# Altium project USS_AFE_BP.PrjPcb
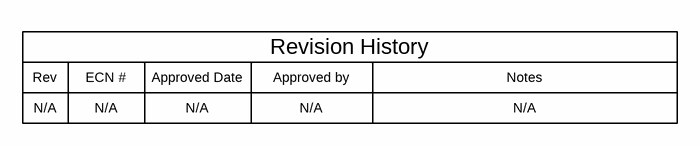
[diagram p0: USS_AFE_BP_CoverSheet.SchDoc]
TID: TIDM-1002; TechSupport: http://www.ti.com/support; SCH_Rev: 1.0; PRJ_Title: USS-AFE-BP; PRJ_Number: USS-AFE-BP; PRJ_Engineer: Luis Reynoso; PRJ_Customer: Public Release; PCB_Rev: RevA; PCB_Layout: A0272600; EVM_Orderable: USS-AFE-BP; CopyrightYear: 2016
3 sheets, 120 parts. Net scope: global (net labels, ports and power ports of the same name join across sheets).
Board file: USS_AFE_BP.PcbDoc
Sheets:
  USS_AFE_BP_CoverSheet.SchDoc
  USS_AFE_BP_AFE.SchDoc
  USS_AFE_BP_Hardware.SchDoc

## Sheet USS_AFE_BP_CoverSheet.SchDoc: Cover Sheet
size 431 x 279 mm; Date: Not shown in title block; ApprovedBy: Not shown in title block; CheckedBy: Not shown in title block; Author: Not shown in title block; CompanyName: Not shown in title block; Engineer: Not shown in title block; Organization: Not shown in title block; Address1: Not shown in title block; Address2: Not shown in title block; Address3: Not shown in title block; Address4: Not shown in title block; DocumentNumber: 1; Revision: Use project parameter SCH_Rev; SheetNumber: 1; SheetTotal: 3; PageSetup: Record=PageOptions¦CenterHorizontal=True¦CenterVertical=True¦PrintScale=1.00¦XCorrection=1.00¦YCorrection=1.00¦PrintKind=0¦BorderSize=5000000¦LeftOffset=0¦BottomOffset=0¦Orientation=2¦PaperLength=1000¦PaperWidth=1000¦Scale=100¦PaperSource=15¦PrintQuality=600¦MediaType=1¦DitherType=10¦PaperKind=Letter¦PrintScaleMode=1

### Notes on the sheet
- Rev
- N/A
- ECN #
- Approved Date
- Approved by
- Revision History
- Notes

## Sheet USS_AFE_BP_AFE.SchDoc: GAS AFE
size 431 x 279 mm; Date: Not shown in title block; ApprovedBy: Not shown in title block; CheckedBy: Not shown in title block; Author: Not shown in title block; CompanyName: Not shown in title block; Engineer: Not shown in title block; Organization: Not shown in title block; Address1: Not shown in title block; Address2: Not shown in title block; Address3: Not shown in title block; Address4: Not shown in title block; DocumentNumber: 1; Revision: Use project parameter SCH_Rev; SheetNumber: 2; SheetTotal: 3; PageSetup: Record=PageOptions¦CenterHorizontal=True¦CenterVertical=True¦PrintScale=0.62¦XCorrection=1.00¦YCorrection=1.00¦PrintKind=0¦BorderSize=5000000¦LeftOffset=0¦BottomOffset=0¦Orientation=2¦PaperLength=1000¦PaperWidth=1000¦Scale=100¦PaperSource=15¦PrintQuality=600¦MediaType=1¦DitherType=10¦PrintScaleMode=1¦PaperKind=Letter
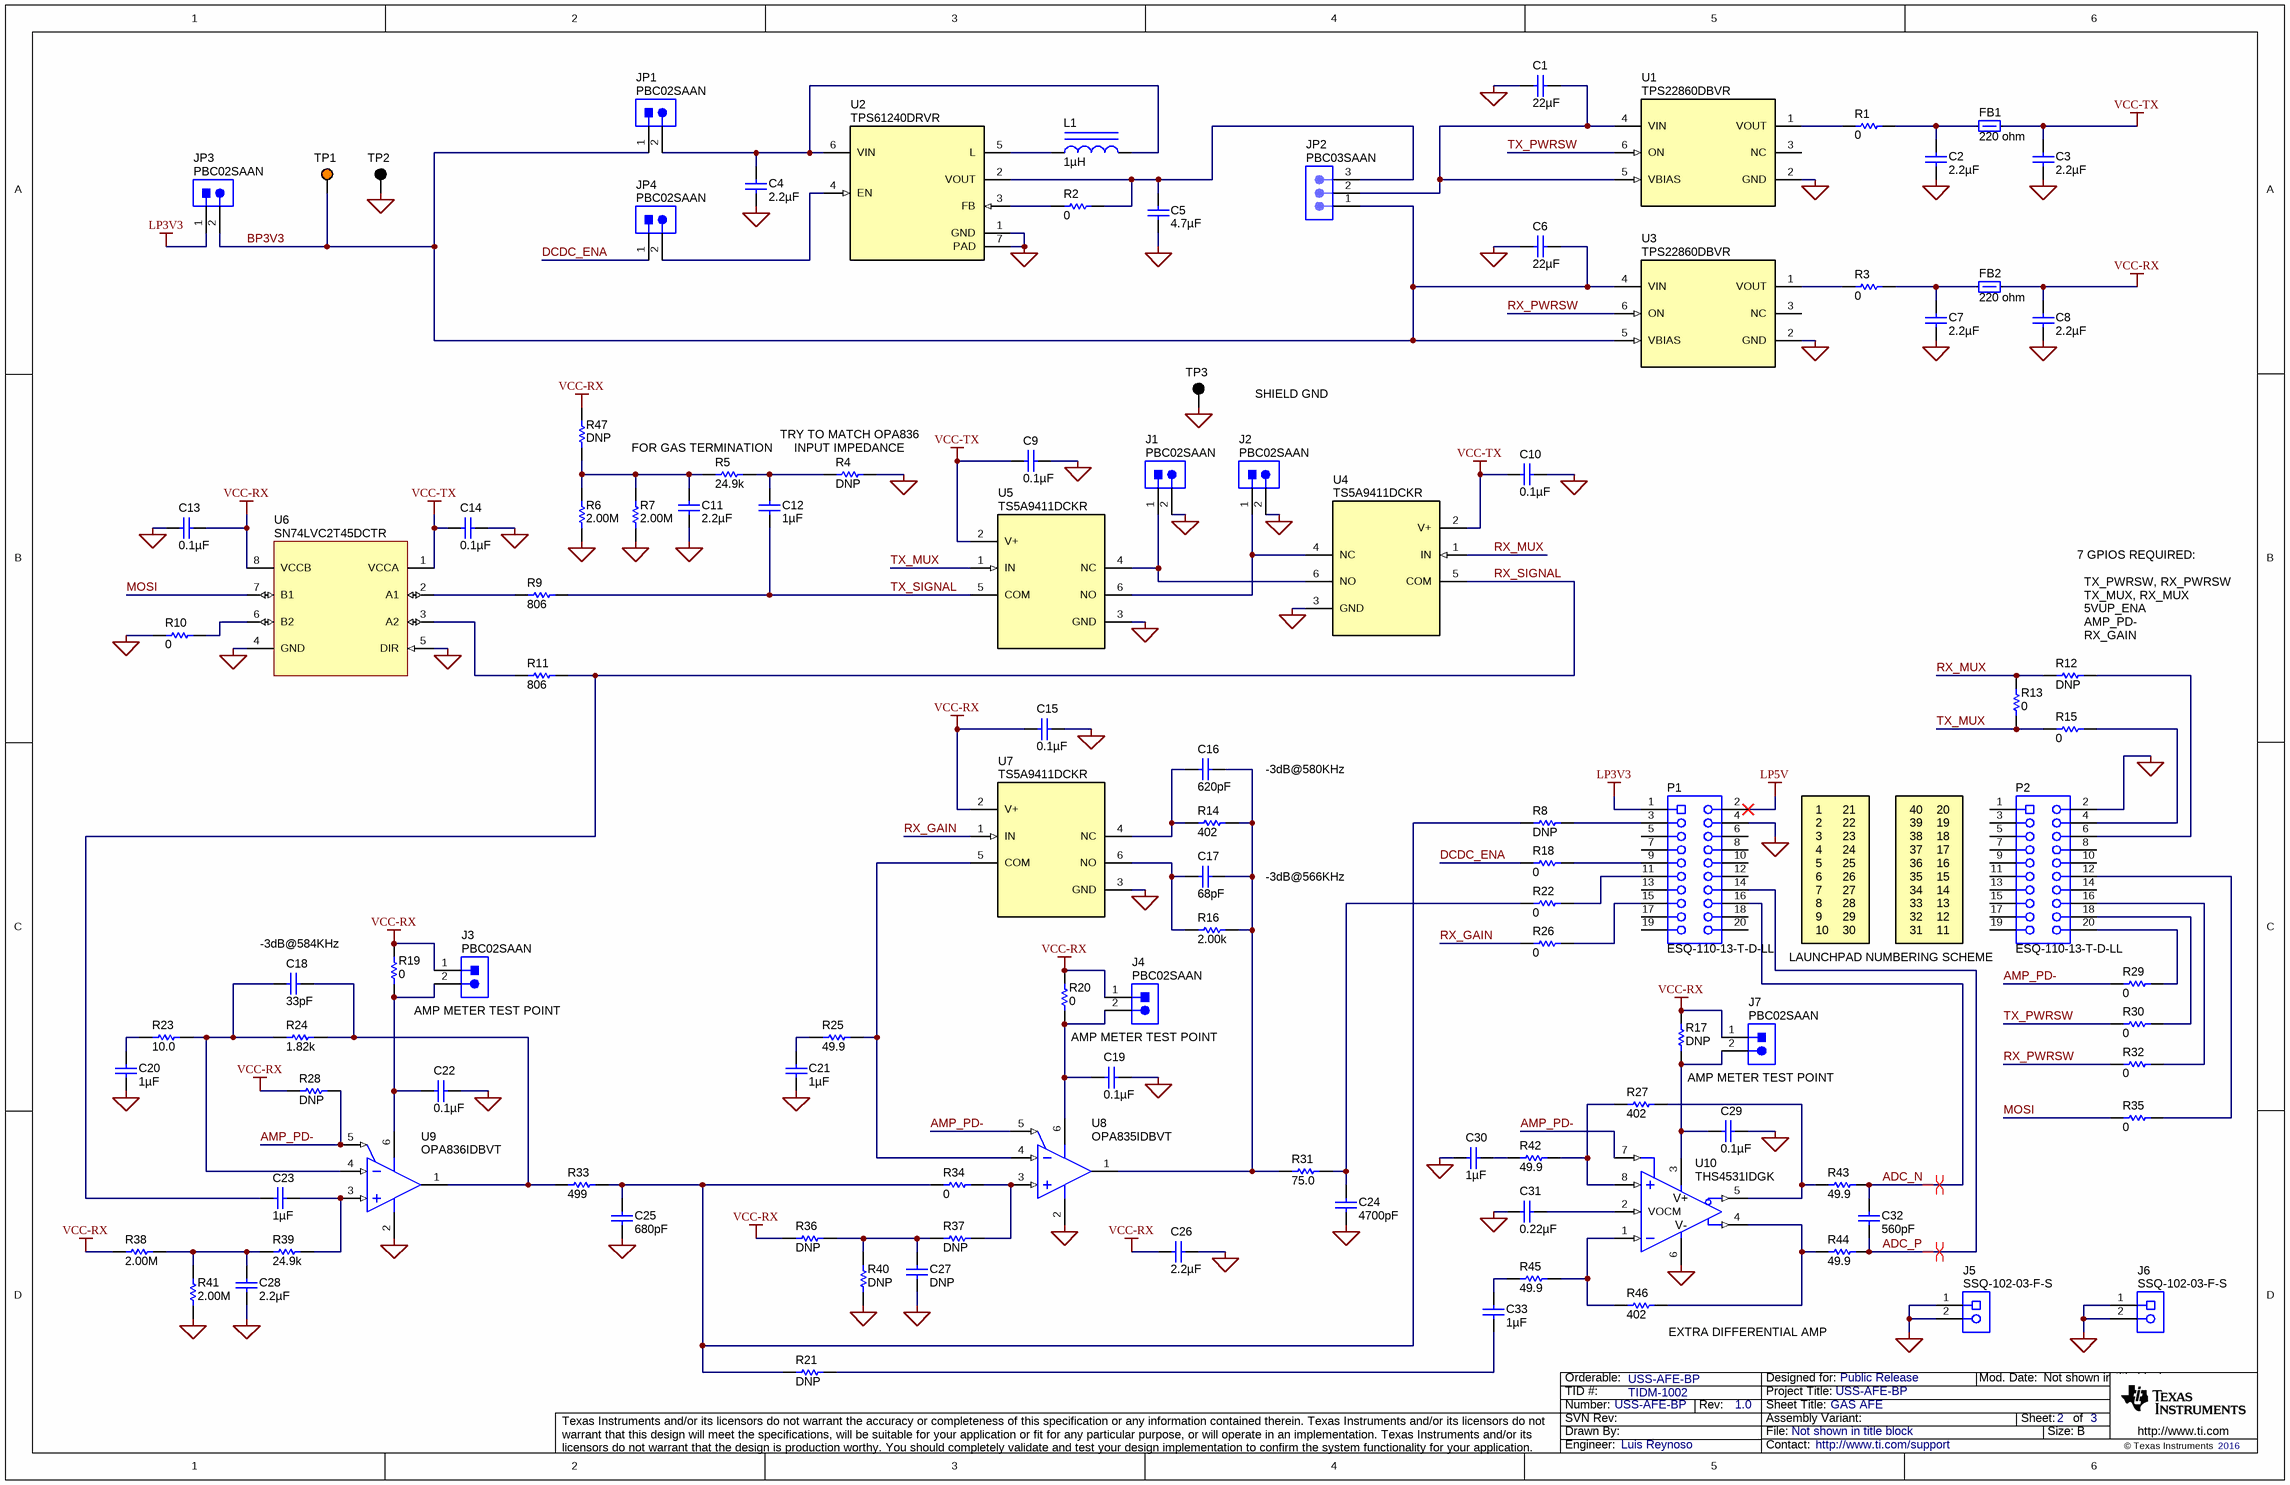
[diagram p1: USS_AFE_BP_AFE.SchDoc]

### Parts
C1  ValueDisplayed: 22µF  [0603]  (hidden comment: CL10A226MP8NUNE)
C2  ValueDisplayed: 2.2µF  [0603]  (hidden comment: GRM188R61C225KE15D)
C3  ValueDisplayed: 2.2µF  [0603]  (hidden comment: GRM188R61C225KE15D)
C4  ValueDisplayed: 2.2µF  [0603]  (hidden comment: GRM188R61C225KE15D)
C5  ValueDisplayed: 4.7µF  [0603]  (hidden comment: GRM188R61C475KAAJ)
C6  ValueDisplayed: 22µF  [0603]  (hidden comment: CL10A226MP8NUNE)
C7  ValueDisplayed: 2.2µF  [0603]  (hidden comment: GRM188R61C225KE15D)
C8  ValueDisplayed: 2.2µF  [0603]  (hidden comment: GRM188R61C225KE15D)
C9  ValueDisplayed: 0.1µF  [0603]  (hidden comment: GRM188R71E104KA01D)
C10  ValueDisplayed: 0.1µF  [0603]  (hidden comment: GRM188R71E104KA01D)
C11  ValueDisplayed: 2.2µF  [0603]  (hidden comment: GRM188R61C225KE15D)
C12  ValueDisplayed: 1µF  [0603]  (hidden comment: GRM188R71C105KA12D)
C13  ValueDisplayed: 0.1µF  [0603]  (hidden comment: GRM188R71E104KA01D)
C14  ValueDisplayed: 0.1µF  [0603]  (hidden comment: GRM188R71E104KA01D)
C15  ValueDisplayed: 0.1µF  [0603]  (hidden comment: GRM188R71E104KA01D)
C16  ValueDisplayed: 620pF  [0603]  (hidden comment: GRM1885C1H621JA01D)
C17  ValueDisplayed: 68pF  [0603]  (hidden comment: GRM1885C1H680JA01D)
C18  ValueDisplayed: 33pF  [0603]  (hidden comment: GRM1885C1H330JA01D)
C19  ValueDisplayed: 0.1µF  [0603]  (hidden comment: GRM188R71E104KA01D)
C20  ValueDisplayed: 1µF  [0603]  (hidden comment: GRM188R71C105KA12D)
C21  ValueDisplayed: 1µF  [0603]  (hidden comment: GRM188R71C105KA12D)
C22  ValueDisplayed: 0.1µF  [0603]  (hidden comment: GRM188R71E104KA01D)
C23  ValueDisplayed: 1µF  [0603]  (hidden comment: GRM188R71C105KA12D)
C24  ValueDisplayed: 4700pF  [0603_HV]  (hidden comment: C0603C472J5RACTU)
C25  ValueDisplayed: 680pF  [0603]  (hidden comment: GRM1885C1H681JA01D)
C26  ValueDisplayed: 2.2µF  [0603]  (hidden comment: GRM188R61C225KE15D)
C27  ValueDisplayed: DNP  [0603]  (hidden comment: GRM188R61C225KE15D)
C28  ValueDisplayed: 2.2µF  [0603]  (hidden comment: GRM188R61C225KE15D)
C29  ValueDisplayed: 0.1µF  [0603]  (hidden comment: GRM188R71E104KA01D)
C30  ValueDisplayed: 1µF  [0603]  (hidden comment: GRM188R71C105KA12D)
C31  ValueDisplayed: 0.22µF  [0603]  (hidden comment: GRM188R71A224KA01D)
C32  ValueDisplayed: 560pF  [0603]  (hidden comment: GRM188R71H561KA01D)
C33  ValueDisplayed: 1µF  [0603]  (hidden comment: GRM188R71C105KA12D)
FB1  value 220 ohm  [0603]  (hidden comment: MPZ1608S221A)
FB2  value 220 ohm  [0603]  (hidden comment: MPZ1608S221A)
J1  PBC02SAAN  [Sullins_PBC02SAAN]
J2  PBC02SAAN  [Sullins_PBC02SAAN]
J3  PBC02SAAN  [Sullins_PBC02SAAN]
J4  PBC02SAAN  [Sullins_PBC02SAAN]
J5  SSQ-102-03-F-S  [Samtec_SSQ-102-03-x-S]
J6  SSQ-102-03-F-S  [Samtec_SSQ-102-03-x-S]
J7  PBC02SAAN  [Sullins_PBC02SAAN]
JP1  PBC02SAAN  [Sullins_PBC02SAAN]
JP2  PBC03SAAN  [PBC03SAAN]
JP3  PBC02SAAN  [Sullins_PBC02SAAN]
JP4  PBC02SAAN  [Sullins_PBC02SAAN]
L1  ValueDisplayed: 1µH  [0805_HV]  (hidden comment: LQM21PN1R0MC0D)
P1  ESQ-110-13-T-D-LL  [Samtec_ESQ-110-13-x-D-LL]
P2  ESQ-110-13-T-D-LL  [Samtec_ESQ-110-13-x-D-LL]
R1  ValueDisplayed: 0  [0603]  (hidden comment: RC0603JR-070RL)
R2  ValueDisplayed: 0  [0603]  (hidden comment: RC0603JR-070RL)
R3  ValueDisplayed: 0  [0603]  (hidden comment: RC0603JR-070RL)
R4  ValueDisplayed: DNP  [0603]  (hidden comment: RC0603FR-07200KL)
R5  ValueDisplayed: 24.9k  [0603]  (hidden comment: RC0603FR-0724K9L)
R6  ValueDisplayed: 2.00M  [0603]  (hidden comment: RC0603FR-072ML)
R7  ValueDisplayed: 2.00M  [0603]  (hidden comment: RC0603FR-072ML)
R8  ValueDisplayed: DNP  [0603]  (hidden comment: RC0603JR-070RL)
R9  ValueDisplayed: 806  [0603]  (hidden comment: RC0603FR-07806RL)
R10  ValueDisplayed: 0  [0603]  (hidden comment: RC0603JR-070RL)
R11  ValueDisplayed: 806  [0603]  (hidden comment: RC0603FR-07806RL)
R12  ValueDisplayed: DNP  [0603]  (hidden comment: RC0603JR-070RL)
R13  ValueDisplayed: 0  [0603]  (hidden comment: RC0603JR-070RL)
R14  ValueDisplayed: 402  [0603]  (hidden comment: RC0603FR-07402RL)
R15  ValueDisplayed: 0  [0603]  (hidden comment: RC0603JR-070RL)
R16  ValueDisplayed: 2.00k  [0603]  (hidden comment: RC0603FR-072KL)
R17  ValueDisplayed: DNP  [0603]  (hidden comment: RC0603JR-070RL)
R18  ValueDisplayed: 0  [0603]  (hidden comment: RC0603JR-070RL)
R19  ValueDisplayed: 0  [0603]  (hidden comment: RC0603JR-070RL)
R20  ValueDisplayed: 0  [0603]  (hidden comment: RC0603JR-070RL)
R21  ValueDisplayed: DNP  [0603]  (hidden comment: RC0603JR-070RL)
R22  ValueDisplayed: 0  [0603]  (hidden comment: RC0603JR-070RL)
R23  ValueDisplayed: 10.0  [0603]  (hidden comment: RC0603FR-0710RL)
R24  ValueDisplayed: 1.82k  [0603]  (hidden comment: RC0603FR-071K82L)
R25  ValueDisplayed: 49.9  [0603]  (hidden comment: RC0603FR-0749R9L)
R26  ValueDisplayed: 0  [0603]  (hidden comment: RC0603JR-070RL)
R27  ValueDisplayed: 402  [0603_HV]  (hidden comment: RC0603FR-07402RL)
R28  ValueDisplayed: DNP  [0603]  (hidden comment: RCG060310K0FKEA)
R29  ValueDisplayed: 0  [0603]  (hidden comment: RC0603JR-070RL)
R30  ValueDisplayed: 0  [0603]  (hidden comment: RC0603JR-070RL)
R31  ValueDisplayed: 75.0  [0603_HV]  (hidden comment: RC0603FR-0775RL)
R32  ValueDisplayed: 0  [0603]  (hidden comment: RC0603JR-070RL)
R33  ValueDisplayed: 499  [0603]  (hidden comment: RC0603FR-07499RL)
R34  ValueDisplayed: 0  [0603]  (hidden comment: RC0603JR-070RL)
R35  ValueDisplayed: 0  [0603]  (hidden comment: RC0603JR-070RL)
R36  ValueDisplayed: DNP  [0603]  (hidden comment: RC0603FR-072ML)
R37  ValueDisplayed: DNP  [0603]  (hidden comment: RC0603FR-0724K9L)
R38  ValueDisplayed: 2.00M  [0603]  (hidden comment: RC0603FR-072ML)
R39  ValueDisplayed: 24.9k  [0603]  (hidden comment: RC0603FR-0724K9L)
R40  ValueDisplayed: DNP  [0603]  (hidden comment: RC0603FR-072ML)
R41  ValueDisplayed: 2.00M  [0603]  (hidden comment: RC0603FR-072ML)
R42  ValueDisplayed: 49.9  [0603]  (hidden comment: RC0603FR-0749R9L)
R43  ValueDisplayed: 49.9  [0603]  (hidden comment: RC0603FR-0749R9L)
R44  ValueDisplayed: 49.9  [0603]  (hidden comment: RC0603FR-0749R9L)
R45  ValueDisplayed: 49.9  [0603]  (hidden comment: RC0603FR-0749R9L)
R46  ValueDisplayed: 402  [0603_HV]  (hidden comment: RC0603FR-07402RL)
R47  ValueDisplayed: DNP  [0603]  (hidden comment: RC0603FR-072ML)
TP1  5003  [Keystone5003]  (value not drawn)
TP2  5001  [Keystone5001]  (value not drawn)
TP3  5001  [Keystone5001]  (value not drawn)
U1  TPS22860DBVR  [DBV0006A_N]
U2  TPS61240DRVR  [DRV0006A]
U3  TPS22860DBVR  [DBV0006A_N]
U4  TS5A9411DCKR  [DCK0006A_N]
U5  TS5A9411DCKR  [DCK0006A_N]
U6  SN74LVC2T45DCTR  [DCT0008A_N]
U7  TS5A9411DCKR  [DCK0006A_N]
U8  OPA835IDBVT  [DBV0006A_N]
U9  OPA836IDBVT  [DBV0006A_N]
U10  THS4531IDGK  [DGK0008A_N]

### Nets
GND: C1.2 C2.2 C3.2 C4.2 C5.2 C6.2 C7.2 C8.2 C9.2 C10.2 C11.1 C13.1 C14.2 C15.2 C19.2 C20.1 C21.1 C22.2 C24.2 C25.2 C26.1 C27.1 C28.1 C29.2 C30.2 C31.2 J1.2 J2.2 J5.1 J5.2 J6.1 J6.2 P1.4 P2.2 R4.2 R6.1 R7.1 R10.2 R40.1 R41.1 TP2.1 TP3.1 U1.2(GND) U2.1(GND) U2.7(PAD) U3.2(GND) U4.3(GND) U5.3(GND) U6.4(GND) U6.5(DIR) U7.3(GND) U8.2(VS-) U9.2(VS-) U10.6(VS-)
LP3V3: JP3.1 P1.1
LP5V: P1.2
VCC-RX: C8.1 C13.2 C15.1 C26.2 FB2.2 J3.1 J4.1 J7.1 R17.2 R19.2 R20.2 R28.1 R36.2 R38.2 R47.2 U6.8(VCCB) U7.2(V+)
VCC-TX: C3.1 C9.1 C10.1 C14.1 FB1.2 U4.2(V+) U5.2(V+) U6.1(VCCA)
ADC_N: C32.1 P1.16 R43.2
ADC_P: C32.2 P1.14 R44.2
AMP_PD-: R28.2 R29.1 U8.5(~{PD}) U9.5(~{PD}) U10.7(~{PD})
BP3V3: C6.1 JP1.1 JP2.1 JP3.2 TP1.1 U3.4(VIN) U3.5(VBIAS)
DCDC_ENA: JP4.1 R18.1
MOSI: R35.1 U6.7(B1)
RX_GAIN: R26.1 U7.1(IN)
RX_MUX: R12.2 R13.1 U4.1(IN)
RX_PWRSW: R32.1 U3.6(ON)
RX_SIGNAL: C23.1 R11.2 U4.5(COM)
TX_MUX: R13.2 R15.2 U5.1(IN)
TX_PWRSW: R30.1 U1.6(ON)
TX_SIGNAL: C12.1 R9.2 U5.5(COM)
NetC1_1: C1.1 JP2.2 U1.4(VIN) U1.5(VBIAS)
NetC2_1: C2.1 FB1.1 R1.1
NetC4_1: C4.1 JP1.2 L1.2 U2.6(VIN)
NetC5_1: C5.1 JP2.3 R2.1 U2.2(VOUT)
NetC7_1: C7.1 FB2.1 R3.1
NetC11_2: C11.2 R5.1 R6.2 R7.2 R47.1
NetC12_2: C12.2 R4.1 R5.2
NetC16_1: C16.1 C17.1 R14.2 R16.2 R31.1 U8.1(VOUT)
NetC16_2: C16.2 R14.1 U7.4(NC)
NetC17_2: C17.2 R16.1 U7.6(NO)
NetC18_1: C18.1 R24.2 R33.1 U9.1(VOUT)
NetC18_2: C18.2 R23.2 R24.1 U9.4(VIN-)
NetC19_1: C19.1 J4.2 R20.1 U8.6(VS+)
NetC20_2: C20.2 R23.1
NetC21_2: C21.2 R25.1
NetC22_1: C22.1 J3.2 R19.1 U9.6(VS+)
NetC23_2: C23.2 R39.2 U9.3(VIN+)
NetC24_1: C24.1 R22.1 R31.2
NetC25_1: C25.1 R8.2 R21.2 R33.2 R34.2
NetC27_2: C27.2 R36.1 R37.1 R40.2
NetC28_2: C28.2 R38.1 R39.1 R41.2
NetC29_1: C29.1 J7.2 R17.1 U10.3(VS+)
NetC30_1: C30.1 R42.1
NetC31_1: C31.1 U10.2(VOCM)
NetC33_1: C33.1 R21.1
NetC33_2: C33.2 R45.1
NetJ1_1: J1.1 U4.6(NO) U5.4(NC)
NetJ2_1: J2.1 U4.4(NC) U5.6(NO)
NetJP4_2: JP4.2 U2.4(EN)
NetL1_1: L1.1 U2.5(L)
NetP1_3: P1.3 R8.1
NetP1_9: P1.9 R18.2
NetP1_11: P1.11 R22.2
NetP1_15: P1.15 R26.2
NetP2_4: P2.4 R15.1
NetP2_6: P2.6 R12.1
NetP2_12: P2.12 R35.2
NetP2_16: P2.16 R32.2
NetP2_18: P2.18 R30.2
NetP2_20: P2.20 R29.2
NetR1_2: R1.2 U1.1(VOUT)
NetR2_2: R2.2 U2.3(FB)
NetR3_2: R3.2 U3.1(VOUT)
NetR9_1: R9.1 U6.2(A1)
NetR10_1: R10.1 U6.6(B2)
NetR11_1: R11.1 U6.3(A2)
NetR25_2: R25.2 U7.5(COM) U8.4(VIN-)
NetR27_1: R27.1 R42.2 U10.8(VIN+)
NetR27_2: R27.2 R43.1 U10.5(VOUT-)
NetR34_1: R34.1 R37.2 U8.3(VIN+)
NetR44_1: R44.1 R46.2 U10.4(VOUT+)
NetR45_2: R45.2 R46.1 U10.1(VIN-)

Not connected (* = marked no-connect by the designer): P1 5 6 7 8 10 12 13 17 18 19 20; P2 1 3 5 7 8 9 10 11 13 14 15 17 19; U1 3(NC); U3 3(NC)

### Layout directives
differential pair: ADC_N, ADC_P

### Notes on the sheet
- (near R4) TRY TO MATCH OPA836
- SHIELD GND
- (near R5) FOR GAS TERMINATION
- (near R4) INPUT IMPEDANCE
- 7 GPIOS REQUIRED:
- 5VUP_ENA
- TX_PWRSW, RX_PWRSW
- TX_MUX, RX_MUX
- (near R12) AMP_PD-
- (near R12) RX_GAIN
- -3dB@580KHz
- 2
- 3
- 1
- 22
- 23
- 21
- 39
- 38
- 40
- 19
- 18
- 20
- -3dB@566KHz
- 4
- 5
- 6
- 7
- 8
- 24
- 25
- 26
- 27
- 28
- 37
- 36
- 35
- 34
- 33
- 17
- 16
- 15
- 14
- 13
- (near C18) -3dB@584KHz
- LAUNCHPAD NUMBERING SCHEME
- 9
- 10
- 29
- 30
- 32
- 31
- 12
- 11
- (near J3) AMP METER TEST POINT
- AMP METER TEST POINT
- (near R46) EXTRA DIFFERENTIAL AMP

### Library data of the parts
C1 C6 = CL10A226MP8NUNE: CAP, CERM, 22 µF, 10 V, +/- 20%, X5R, 0603; Manufacturer: Samsung Electro-Mechanics; Polarized: N; CompType: Capacitor; Value: 22uF; U/M: EA; Cap_F: 0.000022; Tolerance_%: 20; Value1: Unknown; VDC_V: 10; Value2: 10V; TaMin_C: -55; TaMax_C: 85; AEC Category: Q200
C2-C4 C7 C8 C11 C26-C28 = GRM188R61C225KE15D: CAP, CERM, 2.2 µF, 16 V, +/- 10%, X5R, 0603; Manufacturer: MuRata; Polarized: N; CompType: Capacitor; Value: 2.2uF; U/M: EA; Cap_F: 0.0000022; Tolerance_%: 10; Value1: Unknown; VDC_V: 16; Value2: 16V; TaMin_C: -55; TaMax_C: 85
C5 = GRM188R61C475KAAJ: CAP, CERM, 4.7 µF, 16 V, +/- 10%, X5R, 0603; Manufacturer: MuRata; Polarized: N; CompType: Capacitor; Value: 4.7uF; U/M: EA; Cap_F: 0.0000047; Tolerance_%: 10; Value1: Unknown; VDC_V: 16; Value2: 16V; TaMin_C: -55; TaMax_C: 85; AEC Category: Q200
C9 C10 C13-C15 C19 C22 C29 = GRM188R71E104KA01D: CAP, CERM, 0.1 µF, 25 V, +/- 10%, X7R, 0603; Manufacturer: MuRata; Polarized: N; CompType: Capacitor; Value: 0.1uF; U/M: EA; Cap_F: 0.0000001; Tolerance_%: 10; Value1: Unknown; VDC_V: 25; Value2: 25V; TaMin_C: -55; TaMax_C: 125
C12 C20 C21 C23 C30 C33 = GRM188R71C105KA12D: CAP, CERM, 1 µF, 16 V, +/- 10%, X7R, 0603; Manufacturer: MuRata; Polarized: N; CompType: Capacitor; Value: 1uF; U/M: EA; Cap_F: 0.000001; Tolerance_%: 10; ESR_ohm: 0.011; Value1: 0.011 ohm; VDC_V: 16; Value2: 16V; TaMin_C: -55; TaMax_C: 125
C16 = GRM1885C1H621JA01D: CAP, CERM, 620 pF, 50 V, +/- 5%, C0G/NP0, 0603; Manufacturer: MuRata; Polarized: N; CompType: Capacitor; Value: 620pF; U/M: EA; Cap_F: 0.00000000062; Tolerance_%: 5; Value1: Unknown; VDC_V: 50; Value2: 50V; TaMin_C: -55; TaMax_C: 125; AEC Category: Q200
C17 = GRM1885C1H680JA01D: CAP, CERM, 68 pF, 50 V, +/- 5%, C0G/NP0, 0603; Manufacturer: MuRata; Polarized: N; CompType: Capacitor; Value: 68pF; U/M: EA; Cap_F: 0.000000000068; Tolerance_%: 5; Value1: Unknown; VDC_V: 50; Value2: 50V; TaMin_C: -55; TaMax_C: 125; AEC Category: Q200
C18 = GRM1885C1H330JA01D: CAP, CERM, 33 pF, 50 V, +/- 5%, C0G/NP0, 0603; Manufacturer: MuRata; Polarized: N; CompType: Capacitor; Value: 33pF; U/M: EA; Cap_F: 0.000000000033; Tolerance_%: 5; Value1: Unknown; VDC_V: 50; Value2: 50V; TaMin_C: -55; TaMax_C: 125; AEC Category: Q200
C24 = C0603C472J5RACTU: CAP, CERM, 4700 pF, 50 V, +/- 5%, X7R, 0603; Manufacturer: Kemet; Polarized: N; CompType: Capacitor; Value: 4700pF; U/M: EA; Cap_F: 0.0000000047; Tolerance_%: 5; Value1: Unknown; VDC_V: 50; Value2: 50V; TaMin_C: -55; TaMax_C: 125; Cap_Case: 0603; AEC Category: Q200
C25 = GRM1885C1H681JA01D: CAP, CERM, 680 pF, 50 V, +/- 5%, C0G/NP0, 0603; Manufacturer: MuRata; Polarized: N; CompType: Capacitor; Value: 680pF; U/M: EA; Cap_F: 0.00000000068; Tolerance_%: 5; Value1: Unknown; VDC_V: 50; Value2: 50V; TaMin_C: -55; TaMax_C: 125; AEC Category: Q200
C31 = GRM188R71A224KA01D: CAP, CERM, 0.22 µF, 10 V, +/- 10%, X7R, 0603; Manufacturer: MuRata; Polarized: N; CompType: Capacitor; Value: 0.22uF; U/M: EA; Cap_F: 0.00000022; Tolerance_%: 10; Value1: Unknown; Value2: 10V; TaMin_C: -55; TaMax_C: 125; AEC Category: Q200
C32 = GRM188R71H561KA01D: CAP, CERM, 560 pF, 50 V, +/- 10%, X7R, 0603; Manufacturer: MuRata; Polarized: N; CompType: Capacitor; Value: 560pF; U/M: EA; Cap_F: 0.00000000056; Tolerance_%: 10; Value1: Unknown; VDC_V: 50; Value2: 50V; TaMin_C: -55; TaMax_C: 125; AEC Category: Q200
FB1 FB2 = MPZ1608S221A: Ferrite Bead, 220 ohm @ 100 MHz, 2.2 A, 0603; Manufacturer: TDK; Imax_A: 2.2; DCR_ohm: 0.05; Value1: 0.05 ohm; Value2: 2.2A; ZTyp@100MHz_Ohm: 220
J1-J4 J7 JP1 JP3 JP4 = PBC02SAAN: Header, 100mil, 2x1, Gold, TH; Manufacturer: Sullins Connector Solutions; SymbolCreator: a0412235; Pitch_mm: 2.54; Gender: Male; Shrouded: N; Row_Count: 1; Current_A: 3; Voltage_V: 1800; Cert_UL: Y
J5 J6 = SSQ-102-03-F-S: Receptacle, 2.54mm, 2x1, Gold, TH; Manufacturer: Samtec; SymbolCreator: a0412235; Pitch_mm: 2.54; Gender: Female; Row_Count: 1
JP2 = PBC03SAAN: Header, 100mil, 3x1, Gold, TH; Manufacturer: Sullins Connector Solutions
L1 = LQM21PN1R0MC0D: Inductor, Multilayer, Ferrite, 1 µH, 0.8 A, 0.19 ohm, SMD; Manufacturer: MuRata; Value: 1uH; Ind_H: 1.0E-6; Imax_A: 0.8; Irms: 0.8A @ 40C rise; DCR_ohm: 0.19; Value2: 0.8A; AEC Category: Q200
P1 P2 = ESQ-110-13-T-D-LL: Receptacle, 2.54mm, 10x2, Tin, TH; Manufacturer: Samtec; SymbolCreator: a0412235; Pitch_mm: 2.54; Gender: Female; Row_Count: 2; Current_A: 5.7; Voltage_V: 550; Cert_CSA: Y
R1-R3 R8 R10 R12 R13 R15 R17-R22 R26 R29 R30 R32 R34 R35 = RC0603JR-070RL: RES, 0, 5%, 0.1 W, 0603; Manufacturer: Yageo America; CompType: Resistor; Value: 0; Value_Code: 0000; Tolerance_%: 5; Power_W: 0.1; Value2: 0.1W; VDC_V: 50; TempCo: 200 ppm/C; EIA_Code: E24; U/M: EA
R4 = RC0603FR-07200KL: RES, 200 k, 1%, 0.1 W, 0603; Manufacturer: Yageo America; CompType: Resistor; Value: 200k; Res_ohm: 200000; Tolerance_%: 1; Power_W: 0.1; Value2: 0.1W; VDC_V: 150; TempCo: 200 ppm/C; SizeArea_mm2: 1.28; SizeX_mm: 1.6; SizeY_mm: 0.8; EIA_Code: E96; U/M: EA; AEC Category: Q200
R5 R37 R39 = RC0603FR-0724K9L: RES, 24.9 k, 1%, 0.1 W, 0603; Manufacturer: Yageo America; CompType: Resistor; Value: 24.9k; Res_ohm: 24900; Value_Code: 24k9; Tolerance_%: 1; Power_W: 0.1; Value2: 0.1W; VDC_V: 150; TempCo: 200 ppm/C; EIA_Code: E96; U/M: EA; AEC Category: Q200
R6 R7 R36 R38 R40 R41 R47 = RC0603FR-072ML: RES, 2.00 M, 1%, 0.1 W, 0603; Manufacturer: Yageo America; CompType: Resistor; Value: 2.00Meg; Res_ohm: 2000000; Value_Code: 2M00; Tolerance_%: 1; Power_W: 0.1; Value2: 0.1W; VDC_V: 150; TempCo: 200 ppm/C; SizeArea_mm2: 1.28; SizeX_mm: 1.6; SizeY_mm: 0.8; EIA_Code: E96; U/M: EA; AEC Category: Q200
R9 R11 = RC0603FR-07806RL: RES, 806, 1%, 0.1 W, 0603; Manufacturer: Yageo America; CompType: Resistor; Value: 806; Value_Code: 806R; Tolerance_%: 1; Power_W: 0.1; Value2: 0.1W; VDC_V: 150; TempCo: 200 ppm/C; EIA_Code: E96; U/M: EA; AEC Category: Q200
R14 R27 R46 = RC0603FR-07402RL: RES, 402, 1%, 0.1 W, 0603; Manufacturer: Yageo America; CompType: Resistor; Value: 402; Value_Code: 402R; Tolerance_%: 1; Power_W: 0.1; Value2: 0.1W; VDC_V: 150; TempCo: 200 ppm/C; EIA_Code: E96; U/M: EA; AEC Category: Q200
R16 = RC0603FR-072KL: RES, 2.00 k, 1%, 0.1 W, 0603; Manufacturer: Yageo America; CompType: Resistor; Value: 2.00k; Res_ohm: 2000; Value_Code: 2k00; Tolerance_%: 1; Power_W: 0.1; Value2: 0.1W; VDC_V: 150; TempCo: 200 ppm/C; EIA_Code: E96; U/M: EA; AEC Category: Q200
R23 = RC0603FR-0710RL: RES, 10.0, 1%, 0.1 W, 0603; Manufacturer: Yageo America; CompType: Resistor; Value: 10.0; Res_ohm: 10; Value_Code: 10R0; Tolerance_%: 1; Power_W: 0.1; Value2: 0.1W; VDC_V: 150; TempCo: 200 ppm/C; EIA_Code: E96; U/M: EA; AEC Category: Q200
R24 = RC0603FR-071K82L: RES, 1.82 k, 1%, 0.1 W, 0603; Manufacturer: Yageo America; CompType: Resistor; Value: 1.82k; Res_ohm: 1820; Value_Code: 1k82; Tolerance_%: 1; Power_W: 0.1; Value2: 0.1W; VDC_V: 150; TempCo: 200 ppm/C; EIA_Code: E96; U/M: EA; AEC Category: Q200
R25 R42-R45 = RC0603FR-0749R9L: RES, 49.9, 1%, 0.1 W, 0603; Manufacturer: Yageo America; CompType: Resistor; Value: 49.9; Value_Code: 49R9; Tolerance_%: 1; Power_W: 0.1; Value2: 0.1W; VDC_V: 150; TempCo: 200 ppm/C; EIA_Code: E96; U/M: EA; AEC Category: Q200
R28 = RCG060310K0FKEA: RES, 10.0 k, 1%, 0.1 W, 0603; Manufacturer: Vishay Draloric; CompType: Resistor; Value: 10.0k; Res_ohm: 10000; Value_Code: 10k0; Tolerance_%: 1; Power_W: 0.1; Value2: 0.1W; VDC_V: 75; TempCo: 100 ppm/C; EIA_Code: E96; U/M: EA; AEC Category: Q200; AEC Qualified: N
R31 = RC0603FR-0775RL: RES, 75.0, 1%, 0.1 W, 0603; Manufacturer: Yageo America; CompType: Resistor; Value: 75.0; Res_ohm: 75; Value_Code: 75R0; Tolerance_%: 1; Power_W: 0.1; Value2: 0.1W; VDC_V: 150; TempCo: 200 ppm/C; EIA_Code: E96; U/M: EA; AEC Category: Q200
R33 = RC0603FR-07499RL: RES, 499, 1%, 0.1 W, 0603; Manufacturer: Yageo America; CompType: Resistor; Value: 499; Value_Code: 499R; Tolerance_%: 1; Power_W: 0.1; Value2: 0.1W; VDC_V: 150; TempCo: 200 ppm/C; EIA_Code: E96; U/M: EA; AEC Category: Q200
TP1 = 5003: Test Point, Miniature, Orange, TH; Manufacturer: Keystone; CompType: Test Point Loop; U/M: EA
TP2 TP3 = 5001: Test Point, Miniature, Black, TH; Manufacturer: Keystone; CompType: Test Point Loop; U/M: EA
U1 U3 = TPS22860DBVR: Ultra-Low Leakage Load Switch, DBV0006A; Manufacturer: Texas Instruments; SymbolCreator: Altium; CompType: IC; U/M: EA
U2 = TPS61240DRVR: 3.5-MHz High Efficiency Step-Up Converter,  DRV0006A; Alternate PartNumber: TPS61240DRVT; Manufacturer: Texas Instruments; SymbolCreator: a799628; CompType: IC; U/M: EA
U4 U5 U7 = TS5A9411DCKR: 10-Ω SPDT ANALOG SWITCH SINGLE-CHANNEL 2:1 MULTIPLEXER/DEMULTIPLEXER, DCK0006A; Alternate PartNumber: TS5A9411DCKT; Manufacturer: Texas Instruments; SymbolCreator: a0411947; SizeArea_mm2: 4.2; SizeAreaWB_mm2: 9.3; SizeX_mm: 2.1; SizeY_mm: 2; SizeZ_mm: 1.1; CompType: IC; U/M: EA
U6 = SN74LVC2T45DCTR: Dual-Bit Dual-Supply Bus Transceiver With Configurable Voltage Translation and 3-State Outputs, DCT0008A; Alternate PartNumber: SN74LVC2T45DCTT; Manufacturer: Texas Instruments; SymbolCreator: Altium; CompType: IC; U/M: EA
U8 = OPA835IDBVT: Ultra Low Power, Rail-to-Rail Out, Negative Rail In, VFB Amplifier, 2.5 to 5.5 V, -40 to 125 degC, 6-pin SOT23 (DBV6), Green (RoHS & no Sb/Br); Alternate Manufacturer: Texas Instruments; Alternate PartNumber: Equivalent; 2nd Harmonic(dBc): 70; 3rd Harmonic(dBc): 73; @ MHz: 1; BW @ Acl(MHz): 56; Iib(Max)(nA): 400; Io(Typ)(mA): 40; Iq per channel(Max)(mA): 0.25; Settling Time (0.1%)(Typ)(ns): 55; Slew Rate(Typ)(V/us): 160; Sub Family: Audio Operational Amplifier, High Speed Amplifier (>=50MHz), Low Noise Amp (<=10nV/rtHz), Low Offset Voltage Amplifier (<=500uV), Low Power Amp (<=500uA), Low Supply Voltage Amplifier (<=2.7V); Vio(Max)(mV): 0.5; Vn at Flatband(Typ)(nV/rtHz): 9.3; Vs(Max)(V): 5.5; Vs(Min)(V): 2.5
U9 = OPA836IDBVT: Very Low Power, Rail to Rail Out, Negative Rail In, VFB Operational Amplifier, 2.5 to 5.5 V, -40 to 125 degC, 6-pin SOT23 (DBV6), Green (RoHS & no Sb/Br); Alternate Manufacturer: Texas Instruments; Alternate PartNumber: Equivalent; 2nd Harmonic(dBc): 85; 3rd Harmonic(dBc): 105; @ MHz: 1; BW @ Acl(MHz): 205; Iib(Max)(nA): 1000; Io(Typ)(mA): 50; Settling Time (0.1%)(Typ)(ns): 30; Slew Rate(Typ)(V/us): 560; Sub Family: Audio Operational Amplifier, High Output Current Amplifier (>=50mA), High Speed Amplifier (>=50MHz), Low Noise Amp (<=10nV/rtHz), Low Offset Voltage Amplifier (<=500uV), Low Supply Voltage Amplifier (<=2.7V); Vio(Max)(mV): 0.4; Vn at Flatband(Typ)(nV/rtHz): 4.6; Vs(Max)(V): 5.5; Vs(Min)(V): 2.5
U10 = THS4531IDGK: Ultra Low Power, Rail-to-Rail Output, Fully-Differential Amplifier, DGK0008A; Manufacturer: Texas Instruments; SymbolCreator: a0411947; SizeArea_mm2: 15.655; SizeAreaWB_mm2: 35.955; SizeX_mm: 5.05; SizeY_mm: 3.1; SizeZ_mm: 1.1; CompType: IC; U/M: EA

## Sheet USS_AFE_BP_Hardware.SchDoc: Ultrasonic E6 Hardware
size 431 x 279 mm; Date: Not shown in title block; ApprovedBy: Not shown in title block; CheckedBy: Not shown in title block; Author: Not shown in title block; CompanyName: Not shown in title block; Engineer: Not shown in title block; Organization: Not shown in title block; Address1: Not shown in title block; Address2: Not shown in title block; Address3: Not shown in title block; Address4: Not shown in title block; DocumentNumber: 1; Revision: Use project parameter SCH_Rev; SheetNumber: 3; SheetTotal: 3; PageSetup: Record=PageOptions¦CenterHorizontal=True¦CenterVertical=True¦PrintScale=1.00¦XCorrection=1.00¦YCorrection=1.00¦PrintKind=0¦BorderSize=5000000¦LeftOffset=0¦BottomOffset=0¦Orientation=2¦PaperLength=1000¦PaperWidth=1000¦Scale=100¦PaperSource=15¦PrintQuality=600¦MediaType=1¦DitherType=10¦PaperKind=Letter¦PrintScaleMode=1
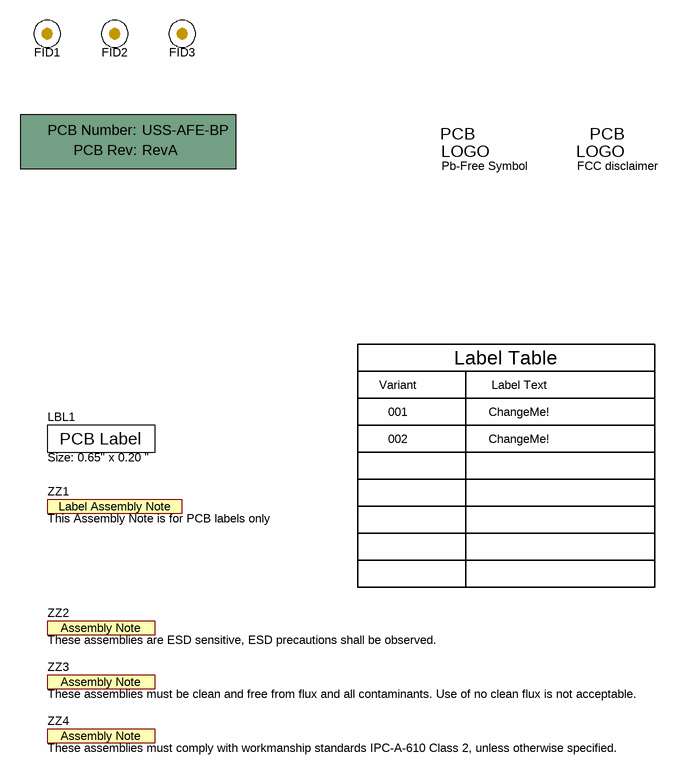
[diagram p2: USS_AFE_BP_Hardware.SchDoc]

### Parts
!PCB1  Printed Circuit Board  (value not drawn)  (mechanical)
FID1  Fiducial  [Fiducial10-20]  (value not drawn)
FID2  Fiducial  [Fiducial10-20]  (value not drawn)
FID3  Fiducial  [Fiducial10-20]  (value not drawn)
LBL1  Size: 0.65" x 0.20 "  [Label_650x200]
Logo2  Pb-Free Symbol  [Pb-Free_Overlay_Small]  (no BOM)
Logo3  FCC disclaimer  [FCC_disclaimer]  (no BOM)
ZZ1  This Assembly Note is for PCB labels only  [AssemblyNoteLabel]  (no BOM)
ZZ2  These assemblies are ESD sensitive, ESD precautions shall be observed.  [AssemblyNote]  (no BOM)
ZZ3  These assemblies must be clean and free from flux and all contaminants. Use of no clean flux is not acceptable.  [AssemblyNote]  (no BOM)
ZZ4  These assemblies must comply with workmanship standards IPC-A-610 Class 2, unless otherwise specified.  [AssemblyNote]  (no BOM)

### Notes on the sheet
- Variant
- Label Table
- Label Text
- 001
- 002
- ChangeMe!

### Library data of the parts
!PCB1 = PCB: Manufacturer: Any; PartNumber: USS-AFE-BP; SymbolCreator: a0412235
FID1-FID3 = Fiducial: Fiducial mark.  There is nothing to buy or mount.; SymbolCreator: codlsc
LBL1 = THT-14-423-10: Thermal Transfer Printable Labels, 0.650" W x 0.200" H - 10,000 per roll; Manufacturer: Brady; SymbolCreator: a0412235; CompType: Label
Logo2 = Pb-Free: SymbolCreator: a0412235
Logo3 = FCC_disclaimer: SymbolCreator: codlsc
ZZ1 = AssemblyNoteLabel: SymbolCreator: a0412235
ZZ2-ZZ4 = AssemblyNote: SymbolCreator: codlsc

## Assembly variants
001: not fitted C27 C32 FID1 FID2 FID3 LBL1 R4 R8 R12 R17 R21 R28 R36 R37 R40 R43 R44 R47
